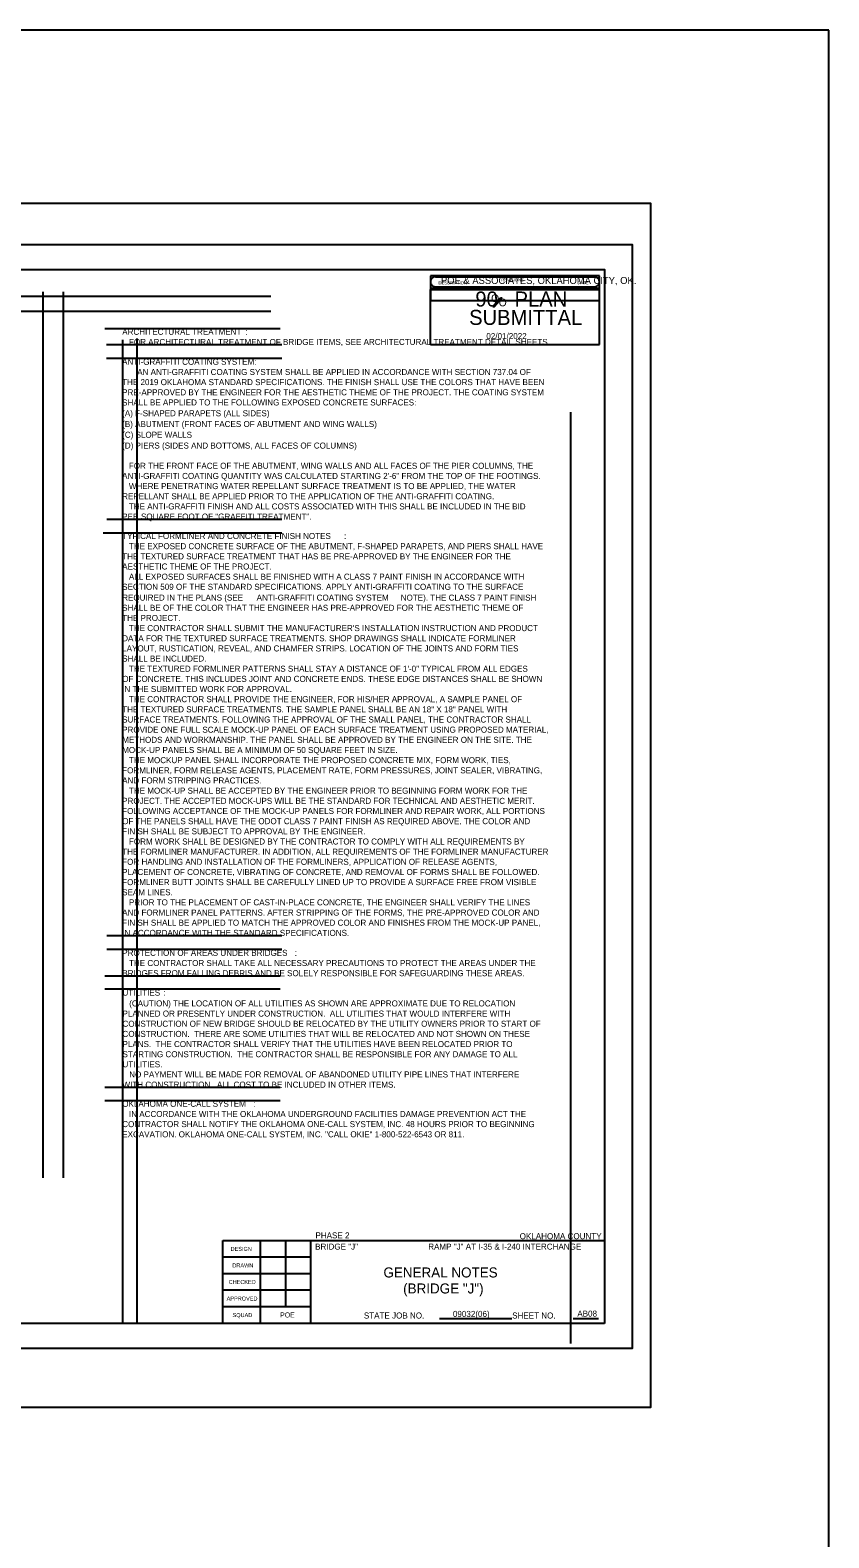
# Model space of a CAD drawing. Extents: x 12312.5 to 12355.9, y 579 to 640.5.
# Drawn here: x 12340.01 to 12355.91, y 610.44 to 640.49 of the extents above; entities that cross this region are included whole.
import ezdxf

# ---------------------------------------------------------------- set-up
doc = ezdxf.new("R2010")
doc.units = 0
for name, color, linetype in [('S', 7, 'Continuous'), ('SHT_Plot_Shape_Full', 7, 'Continuous'), ('SHT_Plot_Shape_Half', 7, 'Continuous'), ('SHT_Sheet_Border', 7, 'Continuous'), ('SHT_Stamp_90_Submit', 7, 'Continuous'), ('SHT_Stamp_Rev_Block', 7, 'Continuous'), ('SHT_Standard_Sheet_Lines', 7, 'Continuous'), ('SHT_Standard_Sheet_Txt', 7, 'Continuous'), ('T', 7, 'Continuous'), ('T-Title', 7, 'Continuous')]:
    doc.layers.add(name, color=color, linetype=linetype)

msp = doc.modelspace()

# ---------------------------------------------------------------- linework, layer by layer
at = {"layer": 'Defpoints'}
for p, q in [((12316.241, 635.187), (12344.799, 635.187)), ((12340.263, 635.276), (12340.263, 617.62)), ((12340.668, 635.276), (12340.668, 617.62)), ((12319.948, 634.891), (12344.799, 634.891)), ((12344.984, 634.537), (12341.495, 634.537)), ((12341.85, 634.316), (12341.85, 614.717)), ((12342.134, 634.344), (12342.134, 614.717)), ((12345.021, 634.214), (12341.532, 634.214)), ((12345.021, 633.945), (12341.532, 633.945)), ((12350.77, 632.876), (12350.77, 614.313)), ((12345.023, 630.735), (12341.533, 630.735)), ((12344.953, 630.465), (12341.464, 630.465)), ((12345.023, 630.465), (12341.533, 630.465)), ((12345.023, 622.439), (12341.533, 622.439)), ((12345.023, 622.169), (12341.533, 622.169)), ((12344.984, 621.636), (12341.495, 621.636)), ((12344.984, 621.374), (12341.495, 621.374)), ((12344.984, 619.415), (12341.495, 619.415)), ((12344.984, 619.153), (12341.495, 619.153))]:
    msp.add_line(p, q, dxfattribs=at)
at = {"layer": 'S'}
msp.add_lwpolyline([(12355.912, 640.488), (12312.476, 640.488), (12312.476, 579.031), (12355.912, 579.031)], close=True, dxfattribs=at)
at = {"layer": 'SHT_Plot_Shape_Full'}
msp.add_lwpolyline([(12316.36, 637.042), (12352.36, 637.042), (12352.36, 613.042), (12316.36, 613.042)], close=True, dxfattribs=at)
at = {"layer": 'SHT_Plot_Shape_Half'}
msp.add_lwpolyline([(12317.998, 636.217), (12351.998, 636.217), (12351.998, 614.217), (12317.998, 614.217)], close=True, dxfattribs=at)
at = {"layer": 'SHT_Sheet_Border'}
for p, q in [((12343.848, 614.717), (12343.848, 616.367)), ((12343.848, 616.367), (12351.448, 616.367)), ((12345.598, 614.717), (12345.598, 616.368))]:
    msp.add_line(p, q, dxfattribs=at)
msp.add_lwpolyline([(12351.448, 614.717), (12319.948, 614.717), (12319.948, 635.717), (12351.448, 635.717)], close=True, dxfattribs=at)
at = {"layer": 'SHT_Stamp_90_Submit'}
for p, q in [((12348.079, 635.572), (12351.245, 635.572)), ((12347.979, 635.322), (12351.345, 635.322)), ((12347.979, 634.223), (12347.979, 635.322)), ((12348.079, 635.372), (12351.245, 635.372)), ((12349.222, 634.984), (12349.377, 635.157)), ((12349.24, 634.984), (12349.395, 635.157)), ((12349.245, 634.984), (12349.4, 635.157)), ((12349.252, 634.984), (12349.408, 635.157)), ((12349.377, 635.157), (12349.408, 635.157)), ((12351.345, 634.223), (12351.345, 635.322)), ((12349.222, 634.984), (12349.252, 634.984)), ((12347.979, 634.223), (12351.345, 634.223))]:
    msp.add_line(p, q, dxfattribs=at)
for centre, start, end in [((12348.079, 635.473), 89.9952, 270), ((12351.245, 635.473), 270, 90.0048)]:
    msp.add_arc(centre, 0.1, start, end, dxfattribs=at)
at = {"layer": 'SHT_Stamp_Rev_Block'}
for p, q in [((12347.979, 635.593), (12347.979, 635.093)), ((12351.345, 635.593), (12347.979, 635.593)), ((12351.345, 635.093), (12351.345, 635.593)), ((12351.345, 635.343), (12347.979, 635.343)), ((12351.345, 635.093), (12347.979, 635.093))]:
    msp.add_line(p, q, dxfattribs=at)
at = {"layer": 'SHT_Standard_Sheet_Lines'}
for p, q in [((12344.598, 614.717), (12344.598, 616.368)), ((12345.098, 615.048), (12345.098, 616.368)), ((12348.159, 614.814), (12349.599, 614.814)), ((12350.823, 614.814), (12351.326, 614.814))]:
    msp.add_line(p, q, dxfattribs=at)
for points in [[(12345.598, 616.037), (12343.848, 616.037)], [(12345.598, 615.707), (12343.848, 615.707)], [(12345.598, 615.377), (12343.848, 615.377)], [(12345.598, 615.047), (12343.848, 615.047)]]:
    msp.add_lwpolyline(points, dxfattribs=at)

# ---------------------------------------------------------------- texts
at = {"layer": 'SHT_Stamp_90_Submit'}
for s, height, p in [('POE & ASSOCIATES, OKLAHOMA CITY, OK.', 0.14, (12348.189, 635.43)), ('90   PLAN', 0.3, (12348.874, 634.98)), ('O', 0.153, (12349.187, 635.069)), ('SUBMITTAL', 0.3, (12348.75, 634.614)), ('O', 0.153, (12349.339, 634.985)), ('02/01/2022', 0.12, (12349.093, 634.332))]:
    msp.add_text(s, height=height, rotation=360, dxfattribs=at).set_placement(p)
at = {"layer": 'SHT_Stamp_Rev_Block'}
for s, p in [('DESCRIPTION', (12348.139, 635.422)), ('REVISIONS', (12349.388, 635.481)), ('DATE', (12350.908, 635.426))]:
    msp.add_text(s, height=0.06, dxfattribs=at).set_placement(p)
at = {"layer": 'SHT_Standard_Sheet_Txt'}
for s, height, p in [('DESIGN', 0.08, (12344, 616.162)), ('DRAWN', 0.08, (12344.035, 615.832)), ('CHECKED', 0.08, (12343.961, 615.502)), ('APPROVED', 0.08, (12343.922, 615.172)), ('SQUAD', 0.08, (12344.039, 614.842)), ('STATE JOB NO.', 0.12, (12346.654, 614.814)), ('SHEET NO. ', 0.12, (12349.607, 614.814))]:
    msp.add_text(s, height=height, dxfattribs=at).set_placement(p)
at = {"layer": 'T'}
for s, height, p in [('ARCHITECTURAL TREATMENT', 0.12, (12341.843, 634.417)), ('   FOR ARCHITECTURAL TREATMENT OF BRIDGE ITEMS, SEE ARCHITECTURAL TREATMENT DETAIL SHEETS.', 0.12, (12341.843, 634.215)), (':', 0.12, (12344.295, 634.417)), ('ANTI-GRAFFITI COATING SYSTEM:', 0.12, (12341.841, 633.819)), ('AN ANTI-GRAFFITI COATING SYSTEM SHALL BE APPLIED IN ACCORDANCE WITH SECTION 737.04 OF ', 0.12, (12342.141, 633.616)), ('THE 2019 OKLAHOMA STANDARD SPECIFICATIONS. THE FINISH SHALL USE THE COLORS THAT HAVE BEEN ', 0.12, (12341.841, 633.414)), ('SHALL BE APPLIED TO THE FOLLOWING EXPOSED CONCRETE SURFACES:', 0.12, (12341.841, 633.009)), ('PRE-APPROVED BY THE ENGINEER FOR THE AESTHETIC THEME OF THE PROJECT. THE COATING SYSTEM ', 0.12, (12341.841, 633.211)), ('(A) F-SHAPED PARAPETS (ALL SIDES)', 0.12, (12341.841, 632.794)), ('(B) ABUTMENT (FRONT FACES OF ABUTMENT AND WING WALLS)', 0.12, (12341.841, 632.579)), ('(C) SLOPE WALLS', 0.12, (12341.841, 632.365)), ('(D) PIERS (SIDES AND BOTTOMS, ALL FACES OF COLUMNS)', 0.12, (12341.841, 632.15)), ('   FOR THE FRONT FACE OF THE ABUTMENT, WING WALLS AND ALL FACES OF THE PIER COLUMNS, THE ', 0.12, (12341.841, 631.747)), ('ANTI-GRAFFITI COATING QUANTITY WAS CALCULATED STARTING 2\'-6" FROM THE TOP OF THE FOOTINGS.', 0.12, (12341.841, 631.545)), ('REPELLANT SHALL BE APPLIED PRIOR TO THE APPLICATION OF THE ANTI-GRAFFITI COATING.', 0.12, (12341.841, 631.14)), ('   WHERE PENETRATING WATER REPELLANT SURFACE TREATMENT IS TO BE APPLIED, THE WATER ', 0.12, (12341.841, 631.342)), ('   THE ANTI-GRAFFITI FINISH AND ALL COSTS ASSOCIATED WITH THIS SHALL BE INCLUDED IN THE BID ', 0.12, (12341.841, 630.937)), ('PER SQUARE FOOT OF "GRAFFITI TREATMENT".', 0.12, (12341.841, 630.735)), ('TYPICAL FORMLINER AND CONCRETE FINISH NOTES', 0.12, (12341.842, 630.348)), (':', 0.12, (12346.26, 630.348)), ('THE TEXTURED SURFACE TREATMENT THAT HAS BE PRE-APPROVED BY THE ENGINEER FOR THE ', 0.12, (12341.842, 629.942)), ('   THE EXPOSED CONCRETE SURFACE OF THE ABUTMENT, F-SHAPED PARAPETS, AND PIERS SHALL HAVE ', 0.12, (12341.842, 630.145)), ('AESTHETIC THEME OF THE PROJECT.', 0.12, (12341.842, 629.74)), ('SECTION 509 OF THE STANDARD SPECIFICATIONS. APPLY ANTI-GRAFFITI COATING TO THE SURFACE ', 0.12, (12341.842, 629.335)), ('   ALL EXPOSED SURFACES SHALL BE FINISHED WITH A CLASS 7 PAINT FINISH IN ACCORDANCE WITH ', 0.12, (12341.842, 629.537)), ('REQUIRED IN THE PLANS (SEE ', 0.12, (12341.842, 629.12)), ('ANTI-GRAFFITI COATING SYSTEM', 0.12, (12344.519, 629.12)), (' NOTE). THE CLASS 7 PAINT FINISH ', 0.12, (12347.343, 629.12)), ('THE PROJECT.', 0.12, (12341.842, 628.715)), ('SHALL BE OF THE COLOR THAT THE ENGINEER HAS PRE-APPROVED FOR THE AESTHETIC THEME OF ', 0.12, (12341.842, 628.917)), ("   THE CONTRACTOR SHALL SUBMIT THE MANUFACTURER'S INSTALLATION INSTRUCTION AND PRODUCT ", 0.12, (12341.842, 628.512)), ('DATA FOR THE TEXTURED SURFACE TREATMENTS. SHOP DRAWINGS SHALL INDICATE FORMLINER ', 0.12, (12341.842, 628.31)), ('SHALL BE INCLUDED.', 0.12, (12341.842, 627.906)), ('LAYOUT, RUSTICATION, REVEAL, AND CHAMFER STRIPS. LOCATION OF THE JOINTS AND FORM TIES ', 0.12, (12341.842, 628.107)), ('   THE TEXTURED FORMLINER PATTERNS SHALL STAY A DISTANCE OF 1\'-0" TYPICAL FROM ALL EDGES ', 0.12, (12341.842, 627.703)), ('OF CONCRETE. THIS INCLUDES JOINT AND CONCRETE ENDS. THESE EDGE DISTANCES SHALL BE SHOWN ', 0.12, (12341.842, 627.501)), ('IN THE SUBMITTED WORK FOR APPROVAL.', 0.12, (12341.842, 627.298)), ('   THE CONTRACTOR SHALL PROVIDE THE ENGINEER, FOR HIS/HER APPROVAL, A SAMPLE PANEL OF ', 0.12, (12341.842, 627.096)), ('THE TEXTURED SURFACE TREATMENTS. THE SAMPLE PANEL SHALL BE AN 18" X 18" PANEL WITH ', 0.12, (12341.842, 626.894)), ('SURFACE TREATMENTS. FOLLOWING THE APPROVAL OF THE SMALL PANEL, THE CONTRACTOR SHALL ', 0.12, (12341.842, 626.691)), ('PROVIDE ONE FULL SCALE MOCK-UP PANEL OF EACH SURFACE TREATMENT USING PROPOSED MATERIAL, ', 0.12, (12341.842, 626.488)), ('METHODS AND WORKMANSHIP. THE PANEL SHALL BE APPROVED BY THE ENGINEER ON THE SITE. THE ', 0.12, (12341.842, 626.286)), ('MOCK-UP PANELS SHALL BE A MINIMUM OF 50 SQUARE FEET IN SIZE.', 0.12, (12341.842, 626.083)), ('   THE MOCKUP PANEL SHALL INCORPORATE THE PROPOSED CONCRETE MIX, FORM WORK, TIES, ', 0.12, (12341.842, 625.881)), ('AND FORM STRIPPING PRACTICES.', 0.12, (12341.842, 625.476)), ('FORMLINER, FORM RELEASE AGENTS, PLACEMENT RATE, FORM PRESSURES, JOINT SEALER, VIBRATING, ', 0.12, (12341.842, 625.678)), ('   THE MOCK-UP SHALL BE ACCEPTED BY THE ENGINEER PRIOR TO BEGINNING FORM WORK FOR THE ', 0.12, (12341.842, 625.273)), ('PROJECT. THE ACCEPTED MOCK-UPS WILL BE THE STANDARD FOR TECHNICAL AND AESTHETIC MERIT. ', 0.12, (12341.842, 625.07)), ('FOLLOWING ACCEPTANCE OF THE MOCK-UP PANELS FOR FORMLINER AND REPAIR WORK, ALL PORTIONS ', 0.12, (12341.842, 624.868)), ('OF THE PANELS SHALL HAVE THE ODOT CLASS 7 PAINT FINISH AS REQUIRED ABOVE. THE COLOR AND ', 0.12, (12341.842, 624.665)), ('FINISH SHALL BE SUBJECT TO APPROVAL BY THE ENGINEER.', 0.12, (12341.842, 624.463)), ('   FORM WORK SHALL BE DESIGNED BY THE CONTRACTOR TO COMPLY WITH ALL REQUIREMENTS BY ', 0.12, (12341.842, 624.26)), ('THE FORMLINER MANUFACTURER. IN ADDITION, ALL REQUIREMENTS OF THE FORMLINER MANUFACTURER ', 0.12, (12341.842, 624.057)), ('FOR HANDLING AND INSTALLATION OF THE FORMLINERS, APPLICATION OF RELEASE AGENTS, ', 0.12, (12341.842, 623.855)), ('PLACEMENT OF CONCRETE, VIBRATING OF CONCRETE, AND REMOVAL OF FORMS SHALL BE FOLLOWED. ', 0.12, (12341.842, 623.652)), ('FORMLINER BUTT JOINTS SHALL BE CAREFULLY LINED UP TO PROVIDE A SURFACE FREE FROM VISIBLE ', 0.12, (12341.842, 623.45)), ('SEAM LINES.', 0.12, (12341.842, 623.249)), ('   PRIOR TO THE PLACEMENT OF CAST-IN-PLACE CONCRETE, THE ENGINEER SHALL VERIFY THE LINES ', 0.12, (12341.842, 623.047)), ('AND FORMLINER PANEL PATTERNS. AFTER STRIPPING OF THE FORMS, THE PRE-APPROVED COLOR AND ', 0.12, (12341.842, 622.844)), ('FINISH SHALL BE APPLIED TO MATCH THE APPROVED COLOR AND FINISHES FROM THE MOCK-UP PANEL, ', 0.12, (12341.842, 622.642)), ('IN ACCORDANCE WITH THE STANDARD SPECIFICATIONS.', 0.12, (12341.842, 622.439)), ('PROTECTION OF AREAS UNDER BRIDGES', 0.12, (12341.844, 622.041)), ('   THE CONTRACTOR SHALL TAKE ALL NECESSARY PRECAUTIONS TO PROTECT THE AREAS UNDER THE ', 0.12, (12341.844, 621.838)), (':', 0.12, (12345.277, 622.041)), ('BRIDGES FROM FALLING DEBRIS AND BE SOLELY RESPONSIBLE FOR SAFEGUARDING THESE AREAS.', 0.12, (12341.844, 621.636)), ('UTILITIES', 0.12, (12341.848, 621.248)), (':', 0.12, (12342.66, 621.248)), ('   (CAUTION) THE LOCATION OF ALL UTILITIES AS SHOWN ARE APPROXIMATE DUE TO RELOCATION ', 0.12, (12341.848, 621.033)), ('CONSTRUCTION OF NEW BRIDGE SHOULD BE RELOCATED BY THE UTILITY OWNERS PRIOR TO START OF ', 0.12, (12341.848, 620.628)), ('PLANNED OR PRESENTLY UNDER CONSTRUCTION.  ALL UTILITIES THAT WOULD INTERFERE WITH ', 0.12, (12341.848, 620.831)), ('CONSTRUCTION.  THERE ARE SOME UTILITIES THAT WILL BE RELOCATED AND NOT SHOWN ON THESE', 0.12, (12341.848, 620.426)), ('STARTING CONSTRUCTION.  THE CONTRACTOR SHALL BE RESPONSIBLE FOR ANY DAMAGE TO ALL ', 0.12, (12341.848, 620.021)), ('PLANS.  THE CONTRACTOR SHALL VERIFY THAT THE UTILITIES HAVE BEEN RELOCATED PRIOR TO ', 0.12, (12341.848, 620.223)), ('UTILITIES.', 0.12, (12341.848, 619.82)), ('WITH CONSTRUCTION.  ALL COST TO BE INCLUDED IN OTHER ITEMS. ', 0.12, (12341.848, 619.415)), ('   NO PAYMENT WILL BE MADE FOR REMOVAL OF ABANDONED UTILITY PIPE LINES THAT INTERFERE ', 0.12, (12341.848, 619.618)), ('OKLAHOMA ONE-CALL SYSTEM', 0.12, (12341.843, 619.033)), ('   IN ACCORDANCE WITH THE OKLAHOMA UNDERGROUND FACILITIES DAMAGE PREVENTION ACT THE ', 0.12, (12341.843, 618.83)), (':', 0.12, (12344.451, 619.033)), ('CONTRACTOR SHALL NOTIFY THE OKLAHOMA ONE-CALL SYSTEM, INC. 48 HOURS PRIOR TO BEGINNING ', 0.12, (12341.843, 618.628)), ('EXCAVATION. OKLAHOMA ONE-CALL SYSTEM, INC. "CALL OKIE" 1-800-522-6543 OR 811.', 0.12, (12341.843, 618.425)), ('PHASE 2', 0.12, (12345.69, 616.411)), ('OKLAHOMA COUNTY', 0.12, (12349.756, 616.395)), ('BRIDGE "J"', 0.12, (12345.683, 616.187)), ('RAMP "J" AT I-35 & I-240 INTERCHANGE', 0.12, (12347.935, 616.187)), ('POE', 0.1, (12344.987, 614.835)), ('09032(06)', 0.12, (12348.427, 614.846)), ('AB08', 0.12, (12350.904, 614.852))]:
    msp.add_text(s, height=height, dxfattribs=at).set_placement(p)
at = {"layer": 'T-Title'}
for s, p in [('GENERAL NOTES', (12347.044, 615.632)), ('(BRIDGE "J")', (12347.436, 615.313))]:
    msp.add_text(s, height=0.2, dxfattribs=at).set_placement(p)

doc.saveas('drawing.dxf')
